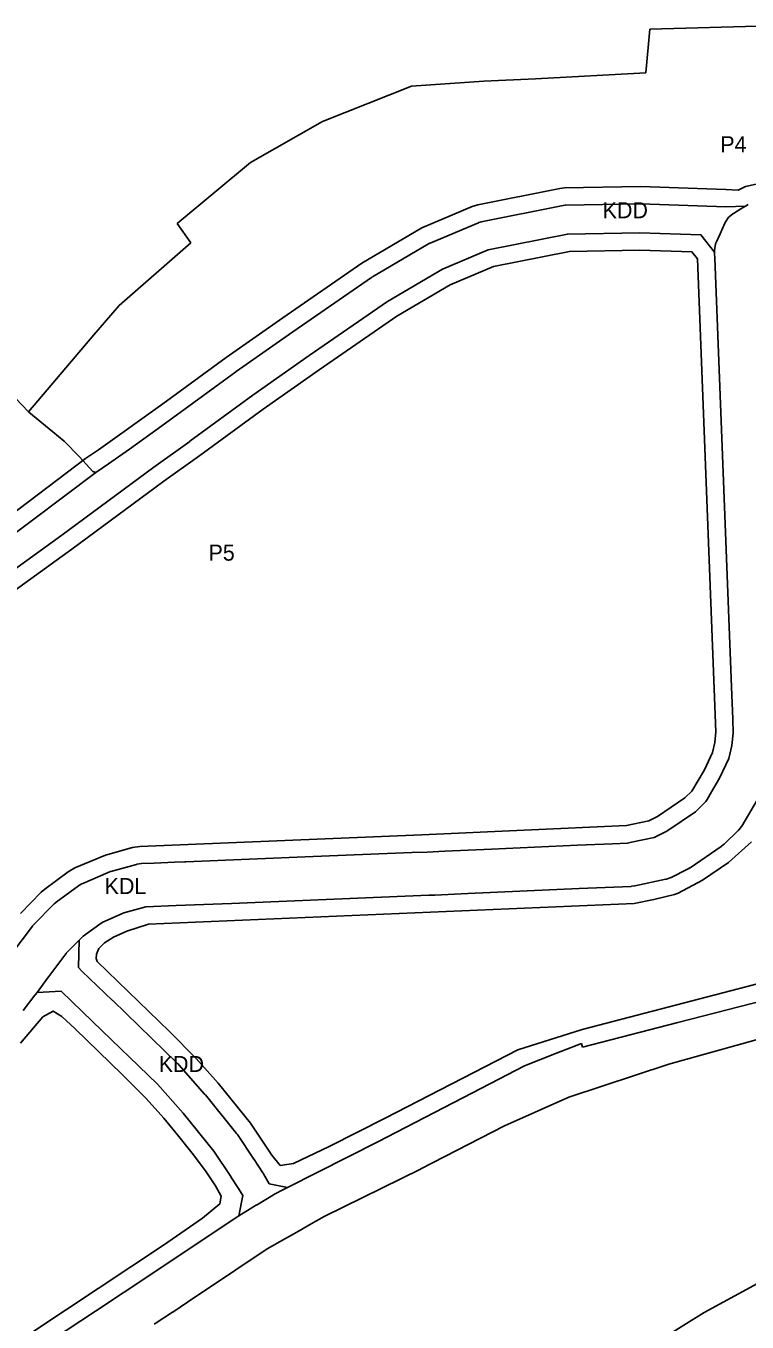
# Model space of a CAD drawing. Extents: x 7428080 to 7432143, y 5545880 to 5549217.
# Drawn here: x 7429660.4 to 7429910.1, y 5546644.6 to 5547093.2 of the extents above; entities that cross this region are included whole.
import ezdxf

# ---------------------------------------------------------------- set-up
doc = ezdxf.new("R2010")
doc.units = 0
for name, color, linetype in [('CZ_L_linie rozgraniczające tereny o różnym przeznaczeniu oraz różnych warunkach ich zabudowy i zagospodarowania', 7, 'Continuous'), ('CZ_L_maksymalne nieprzekraczalne linie zabudowy', 7, 'Continuous'), ('CZ_L_opisy_linie rozgraniczające tereny o różnym przeznaczeniu oraz różnych warunkach ich zabudowy i zagospodarowania', 7, 'Continuous')]:
    doc.layers.add(name, color=color, linetype=linetype)

msp = doc.modelspace()

# ---------------------------------------------------------------- linework, layer by layer
at = {"layer": 'CZ_L_linie rozgraniczające tereny o różnym przeznaczeniu oraz różnych warunkach ich zabudowy i zagospodarowania'}
for p, q in [((7429874.96, 5547076.96), (7429876.37, 5547092.06)), ((7429876.37, 5547092.06), (7429917.87, 5547093.18)), ((7429793.83, 5547072.3), (7429818.9, 5547074.03)), ((7429818.9, 5547074.03), (7429836.84, 5547074.85)), ((7429836.84, 5547074.85), (7429874.96, 5547076.96)), ((7429763.03, 5547060.05), (7429793.83, 5547072.3)), ((7429738.12, 5547045.86), (7429763.03, 5547060.05)), ((7429712.77, 5547024.79), (7429738.12, 5547045.86)), ((7429846.36, 5547031.02), (7429817.99, 5547025.37)), ((7429847.13, 5547031.12), (7429846.36, 5547031.02)), ((7429847.19, 5547031.11), (7429847.13, 5547031.12)), ((7429847.24, 5547031.12), (7429847.19, 5547031.11)), ((7429872.9, 5547031.63), (7429847.24, 5547031.12)), ((7429873.05, 5547031.61), (7429872.9, 5547031.63)), ((7429873.17, 5547031.63), (7429873.05, 5547031.61)), ((7429902.73, 5547030.62), (7429873.17, 5547031.63)), ((7429909.53, 5547030.84), (7429902.73, 5547030.62)), ((7429910.5, 5547031.42), (7429909.53, 5547030.84)), ((7429717.49, 5547018.12), (7429712.77, 5547024.79)), ((7429817.03, 5547025.08), (7429800.36, 5547018.04)), ((7429817.2, 5547025.11), (7429817.03, 5547025.08)), ((7429817.99, 5547025.37), (7429817.2, 5547025.11)), ((7429692.68, 5546996.37), (7429717.49, 5547018.12)), ((7429799.78, 5547017.75), (7429780.38, 5547006.37)), ((7429800.21, 5547017.98), (7429799.78, 5547017.75)), ((7429800.3, 5547018), (7429800.21, 5547017.98)), ((7429800.36, 5547018.04), (7429800.3, 5547018)), ((7429898.8, 5547014.91), (7429898.82, 5547014.42)), ((7429898.82, 5547014.42), (7429898.88, 5547012.83)), ((7429898.88, 5547012.83), (7429904.65, 5546864.42)), ((7429780.07, 5547006.17), (7429752.77, 5546987.33)), ((7429780.29, 5547006.3), (7429780.07, 5547006.17)), ((7429780.38, 5547006.37), (7429780.29, 5547006.3)), ((7429683.9, 5546986.22), (7429692.68, 5546996.37)), ((7429661.31, 5546959.61), (7429683.9, 5546986.22)), ((7429752.73, 5546987.3), (7429733.17, 5546973.53)), ((7429752.75, 5546987.31), (7429752.73, 5546987.3)), ((7429752.77, 5546987.33), (7429752.75, 5546987.31)), ((7429733.09, 5546973.48), (7429711.26, 5546957.51)), ((7429733.13, 5546973.5), (7429733.09, 5546973.48)), ((7429733.17, 5546973.53), (7429733.13, 5546973.5)), ((7429654.57, 5546966.64), (7429661.31, 5546959.61)), ((7429661.43, 5546959.5), (7429661.31, 5546959.61)), ((7429669.66, 5546952.68), (7429661.43, 5546959.5)), ((7429711.26, 5546957.51), (7429705.32, 5546953.27)), ((7429673.58, 5546949.45), (7429669.66, 5546952.68)), ((7429705.32, 5546953.27), (7429696.19, 5546946.75)), ((7429678.95, 5546944.02), (7429673.58, 5546949.45)), ((7429683.5, 5546938.95), (7429678.95, 5546944.02)), ((7429696.19, 5546946.75), (7429688.95, 5546941.57)), ((7429684.54, 5546938.62), (7429651.42, 5546913.65)), ((7429684.54, 5546938.62), (7429683.5, 5546938.95)), ((7429688.95, 5546941.57), (7429684.54, 5546938.62)), ((7429704.61, 5546940.47), (7429704.62, 5546940.48)), ((7429904.65, 5546864.42), (7429904.65, 5546864.42)), ((7429904.65, 5546864.42), (7429904.65, 5546864.41)), ((7429904.65, 5546864.41), (7429905.1, 5546853.23)), ((7429905.1, 5546853.23), (7429905.29, 5546848.45)), ((7429904.83, 5546844.15), (7429903.75, 5546839.6)), ((7429905.29, 5546848.45), (7429904.83, 5546844.15)), ((7429903.75, 5546839.6), (7429900.58, 5546832.8)), ((7429900.58, 5546832.8), (7429897.77, 5546828.05)), ((7429897.77, 5546828.05), (7429896.25, 5546825.48)), ((7429895.83, 5546824.76), (7429892.18, 5546821.22)), ((7429896.25, 5546825.48), (7429895.83, 5546824.76)), ((7429913.68, 5546825.49), (7429908.23, 5546816.26)), ((7429892.18, 5546821.22), (7429882.62, 5546814.75)), ((7429882, 5546814.39), (7429877.89, 5546812.31)), ((7429882.3, 5546814.54), (7429882, 5546814.39)), ((7429882.62, 5546814.75), (7429882.3, 5546814.54)), ((7429906.99, 5546814.7), (7429902.15, 5546810)), ((7429907.01, 5546814.73), (7429906.99, 5546814.7)), ((7429907.05, 5546814.76), (7429907.01, 5546814.73)), ((7429907.13, 5546814.86), (7429907.05, 5546814.76)), ((7429907.28, 5546814.99), (7429907.13, 5546814.86)), ((7429907.38, 5546815.11), (7429907.28, 5546814.99)), ((7429908.14, 5546816.13), (7429907.38, 5546815.11)), ((7429908.17, 5546816.18), (7429908.14, 5546816.13)), ((7429908.23, 5546816.26), (7429908.17, 5546816.18)), ((7429821.53, 5546808.29), (7429805.37, 5546807.55)), ((7429851.32, 5546809.65), (7429821.53, 5546808.29)), ((7429851.34, 5546809.65), (7429851.32, 5546809.65)), ((7429851.32, 5546809.65), (7429851.32, 5546809.65)), ((7429851.32, 5546809.65), (7429851.32, 5546809.65)), ((7429851.35, 5546809.65), (7429851.34, 5546809.65)), ((7429863.48, 5546810.14), (7429851.35, 5546809.65)), ((7429868.7, 5546810.35), (7429863.48, 5546810.14)), ((7429870.11, 5546810.65), (7429868.7, 5546810.35)), ((7429877.89, 5546812.31), (7429870.11, 5546810.65)), ((7429901.13, 5546809.17), (7429890.31, 5546801.84)), ((7429901.21, 5546809.23), (7429901.13, 5546809.17)), ((7429901.27, 5546809.27), (7429901.21, 5546809.23)), ((7429901.8, 5546809.73), (7429901.27, 5546809.27)), ((7429901.96, 5546809.84), (7429901.8, 5546809.73)), ((7429902.1, 5546809.96), (7429901.96, 5546809.84)), ((7429902.15, 5546810), (7429902.1, 5546809.96)), ((7429715.38, 5546803.87), (7429711.79, 5546803.72)), ((7429715.73, 5546803.88), (7429715.38, 5546803.87)), ((7429759.79, 5546805.67), (7429715.73, 5546803.88)), ((7429793.99, 5546807.06), (7429759.79, 5546805.67)), ((7429799.27, 5546807.27), (7429793.99, 5546807.06)), ((7429805.37, 5546807.55), (7429799.27, 5546807.27)), ((7429688.86, 5546800.18), (7429680.02, 5546796.38)), ((7429688.9, 5546800.19), (7429688.86, 5546800.18)), ((7429689.07, 5546800.24), (7429688.9, 5546800.19)), ((7429689.7, 5546800.48), (7429689.07, 5546800.24)), ((7429689.73, 5546800.48), (7429689.7, 5546800.48)), ((7429689.81, 5546800.51), (7429689.73, 5546800.48)), ((7429698.71, 5546802.99), (7429689.81, 5546800.51)), ((7429698.81, 5546803.01), (7429698.71, 5546802.99)), ((7429698.88, 5546803.03), (7429698.81, 5546803.01)), ((7429700.25, 5546803.24), (7429698.88, 5546803.03)), ((7429700.42, 5546803.26), (7429700.25, 5546803.24)), ((7429704.73, 5546803.43), (7429700.42, 5546803.26)), ((7429711.79, 5546803.72), (7429704.73, 5546803.43)), ((7429889.48, 5546801.36), (7429883.78, 5546798.48)), ((7429889.52, 5546801.38), (7429889.48, 5546801.36)), ((7429889.71, 5546801.5), (7429889.52, 5546801.38)), ((7429890.21, 5546801.78), (7429889.71, 5546801.5)), ((7429890.23, 5546801.8), (7429890.21, 5546801.78)), ((7429890.31, 5546801.84), (7429890.23, 5546801.8)), ((7429678.57, 5546795.55), (7429670.85, 5546789.94)), ((7429678.65, 5546795.6), (7429678.57, 5546795.55)), ((7429678.69, 5546795.63), (7429678.65, 5546795.6)), ((7429679.7, 5546796.23), (7429678.69, 5546795.63)), ((7429679.83, 5546796.29), (7429679.7, 5546796.23)), ((7429679.91, 5546796.32), (7429679.83, 5546796.29)), ((7429679.98, 5546796.36), (7429679.91, 5546796.32)), ((7429680, 5546796.37), (7429679.98, 5546796.36)), ((7429680.02, 5546796.38), (7429680, 5546796.37)), ((7429869.94, 5546795.39), (7429851.98, 5546794.66)), ((7429870.07, 5546795.4), (7429869.94, 5546795.39)), ((7429871.07, 5546795.53), (7429870.07, 5546795.4)), ((7429871.1, 5546795.54), (7429871.07, 5546795.53)), ((7429871.2, 5546795.55), (7429871.1, 5546795.54)), ((7429881.96, 5546797.84), (7429871.2, 5546795.55)), ((7429882.05, 5546797.87), (7429881.96, 5546797.84)), ((7429882.12, 5546797.88), (7429882.05, 5546797.87)), ((7429883.39, 5546798.31), (7429882.12, 5546797.88)), ((7429883.55, 5546798.37), (7429883.39, 5546798.31)), ((7429883.65, 5546798.43), (7429883.55, 5546798.37)), ((7429883.73, 5546798.46), (7429883.65, 5546798.43)), ((7429883.75, 5546798.47), (7429883.73, 5546798.46)), ((7429883.78, 5546798.48), (7429883.75, 5546798.47)), ((7429799.9, 5546792.29), (7429731.51, 5546789.51)), ((7429799.91, 5546792.29), (7429799.9, 5546792.29)), ((7429799.93, 5546792.29), (7429799.91, 5546792.29)), ((7429799.94, 5546792.29), (7429799.93, 5546792.29)), ((7429799.93, 5546792.29), (7429799.93, 5546792.29)), ((7429801.91, 5546792.38), (7429799.94, 5546792.29)), ((7429813.43, 5546792.9), (7429801.91, 5546792.38)), ((7429851.98, 5546794.66), (7429813.43, 5546792.9)), ((7429669.9, 5546789.12), (7429663.29, 5546782.37)), ((7429669.93, 5546789.14), (7429669.9, 5546789.12)), ((7429670.11, 5546789.3), (7429669.93, 5546789.14)), ((7429670.15, 5546789.33), (7429670.11, 5546789.3)), ((7429670.73, 5546789.85), (7429670.15, 5546789.33)), ((7429670.78, 5546789.88), (7429670.73, 5546789.85)), ((7429670.85, 5546789.94), (7429670.78, 5546789.88)), ((7429694.32, 5546786.2), (7429686.71, 5546782.93)), ((7429701.9, 5546788.31), (7429694.32, 5546786.2)), ((7429712.4, 5546788.73), (7429701.9, 5546788.31)), ((7429731.51, 5546789.51), (7429712.4, 5546788.73)), ((7429662.65, 5546781.62), (7429651.62, 5546766.91)), ((7429662.69, 5546781.67), (7429662.65, 5546781.62)), ((7429662.7, 5546781.68), (7429662.69, 5546781.67)), ((7429663.09, 5546782.15), (7429662.7, 5546781.68)), ((7429663.11, 5546782.17), (7429663.09, 5546782.15)), ((7429663.14, 5546782.21), (7429663.11, 5546782.17)), ((7429663.21, 5546782.27), (7429663.14, 5546782.21)), ((7429663.26, 5546782.34), (7429663.21, 5546782.27)), ((7429663.28, 5546782.35), (7429663.26, 5546782.34)), ((7429663.29, 5546782.37), (7429663.28, 5546782.35)), ((7429686.71, 5546782.93), (7429680.18, 5546778.18)), ((7429679.93, 5546777.93), (7429678.82, 5546776.79)), ((7429680.18, 5546778.18), (7429679.93, 5546777.93)), ((7429674.35, 5546772.23), (7429678.82, 5546776.79)), ((7429678.82, 5546776.79), (7429678.62, 5546767.27)), ((7429668.32, 5546764.19), (7429673.86, 5546771.57)), ((7429673.86, 5546771.57), (7429674.28, 5546772.14)), ((7429674.28, 5546772.14), (7429674.3, 5546772.16)), ((7429674.3, 5546772.16), (7429674.35, 5546772.23)), ((7429664.21, 5546758.69), (7429667.86, 5546763.57)), ((7429667.86, 5546763.57), (7429668.3, 5546764.15)), ((7429668.3, 5546764.15), (7429668.32, 5546764.19)), ((7429678.62, 5546767.27), (7429679.73, 5546766.06)), ((7429679.73, 5546766.06), (7429690.38, 5546755.88)), ((7429664.21, 5546758.69), (7429672.53, 5546759.11)), ((7429672.53, 5546759.11), (7429672.58, 5546759.06)), ((7429672.58, 5546759.06), (7429683.46, 5546748.67)), ((7429659.42, 5546752.44), (7429663.45, 5546757.68)), ((7429663.45, 5546757.68), (7429663.54, 5546757.81)), ((7429663.54, 5546757.81), (7429663.55, 5546757.82)), ((7429663.55, 5546757.82), (7429663.56, 5546757.83)), ((7429663.56, 5546757.83), (7429663.6, 5546757.88)), ((7429663.6, 5546757.88), (7429664.21, 5546758.69)), ((7429690.38, 5546755.88), (7429690.41, 5546755.86)), ((7429690.41, 5546755.86), (7429713.02, 5546733.95)), ((7429886.04, 5546748.22), (7429924.76, 5546758.19)), ((7429683.46, 5546748.67), (7429705.91, 5546726.91)), ((7429853.09, 5546739.73), (7429886.04, 5546748.22)), ((7429934.88, 5546748.35), (7429882.96, 5546733.84)), ((7429844.07, 5546737.68), (7429852.75, 5546741.04)), ((7429852.75, 5546741.04), (7429853.09, 5546739.73)), ((7429832.96, 5546733.29), (7429844.07, 5546737.68)), ((7429713.02, 5546733.95), (7429713.16, 5546733.81)), ((7429713.16, 5546733.81), (7429713.29, 5546733.66)), ((7429713.29, 5546733.66), (7429722.36, 5546723.36)), ((7429818.1, 5546725.51), (7429832.96, 5546733.29)), ((7429882.96, 5546733.84), (7429848.3, 5546722.48)), ((7429705.91, 5546726.91), (7429714.78, 5546716.83)), ((7429722.36, 5546723.36), (7429722.44, 5546723.26)), ((7429722.44, 5546723.26), (7429722.49, 5546723.21)), ((7429722.49, 5546723.21), (7429733.33, 5546709.84)), ((7429782.17, 5546707.01), (7429818.1, 5546725.51)), ((7429848.3, 5546722.48), (7429826.04, 5546712.45)), ((7429714.78, 5546716.83), (7429725.42, 5546703.73)), ((7429733.33, 5546709.84), (7429733.49, 5546709.64)), ((7429733.49, 5546709.64), (7429733.62, 5546709.46)), ((7429826.04, 5546712.45), (7429797.11, 5546697.57)), ((7429733.62, 5546709.46), (7429739.24, 5546701)), ((7429750.95, 5546691.21), (7429782.17, 5546707.01)), ((7429725.42, 5546703.73), (7429731.27, 5546694.94)), ((7429739.24, 5546701), (7429739.38, 5546700.8)), ((7429739.38, 5546700.8), (7429742.44, 5546696.2)), ((7429742.44, 5546696.2), (7429742.5, 5546696.11)), ((7429797.03, 5546697.52), (7429763.67, 5546681.14)), ((7429797.07, 5546697.56), (7429797.03, 5546697.52)), ((7429797.11, 5546697.57), (7429797.07, 5546697.56)), ((7429731.27, 5546694.94), (7429731.34, 5546694.82)), ((7429731.34, 5546694.82), (7429734.02, 5546690.8)), ((7429742.5, 5546696.11), (7429742.6, 5546695.93)), ((7429742.6, 5546695.93), (7429744.59, 5546692.47)), ((7429744.59, 5546692.47), (7429750.95, 5546691.21)), ((7429734.02, 5546690.8), (7429735.44, 5546688.34)), ((7429735.44, 5546688.34), (7429734.05, 5546681.31)), ((7429746.62, 5546688.95), (7429740.23, 5546685.1)), ((7429746.63, 5546688.93), (7429746.62, 5546688.95)), ((7429749.12, 5546690.27), (7429746.63, 5546688.93)), ((7429750.95, 5546691.21), (7429749.12, 5546690.28)), ((7429749.12, 5546690.28), (7429749.12, 5546690.27)), ((7429738.06, 5546683.78), (7429734.05, 5546681.31)), ((7429740.19, 5546685.15), (7429738.05, 5546683.8)), ((7429738.05, 5546683.8), (7429738.06, 5546683.78)), ((7429740.23, 5546685.1), (7429740.19, 5546685.15)), ((7429733.43, 5546680.94), (7429714.83, 5546668.51)), ((7429734.05, 5546681.31), (7429733.43, 5546680.94)), ((7429760, 5546679.05), (7429754.16, 5546675.73)), ((7429763.67, 5546681.14), (7429760, 5546679.05)), ((7429754.16, 5546675.73), (7429750.2, 5546673.48)), ((7429743.94, 5546669.92), (7429733.09, 5546662.72)), ((7429750.2, 5546673.48), (7429743.94, 5546669.92)), ((7429714.83, 5546668.51), (7429703.96, 5546661.25)), ((7429703.96, 5546661.25), (7429684.51, 5546648.33)), ((7429733.09, 5546662.72), (7429721.8, 5546655.21)), ((7429895.22, 5546647.94), (7429920.47, 5546661.62)), ((7429718.88, 5546653.25), (7429711.22, 5546648.04)), ((7429721.8, 5546655.21), (7429718.88, 5546653.25)), ((7429684.51, 5546648.33), (7429664.19, 5546634.98)), ((7429711.15, 5546647.99), (7429704.83, 5546643.84)), ((7429711.17, 5546648.01), (7429711.15, 5546647.99)), ((7429711.22, 5546648.04), (7429711.17, 5546648.01)), ((7429881.09, 5546639.13), (7429895.22, 5546647.94))]:
    msp.add_line(p, q, dxfattribs=at)
for points in [[(7429909.53, 5547030.84), (7429907.9, 5547029.86), (7429905.33, 5547028.3), (7429905.25, 5547028.24), (7429905.15, 5547028.18), (7429903.84, 5547027.11), (7429903.69, 5547026.96), (7429903.54, 5547026.77), (7429902.48, 5547025.17), (7429902.41, 5547025.02), (7429902.37, 5547024.96), (7429900.7, 5547021.25), (7429899.45, 5547018.49), (7429899.44, 5547018.44), (7429899.44, 5547018.44), (7429899.41, 5547018.39), (7429899.37, 5547018.24), (7429899.31, 5547018.12), (7429899.25, 5547017.99), (7429899.24, 5547017.96), (7429899.18, 5547017.71), (7429898.81, 5547015.41), (7429898.8, 5547015.12), (7429898.8, 5547014.94), (7429898.8, 5547014.92), (7429898.8, 5547014.91)], [(7429575.21, 5546869.82), (7429606.33, 5546874.9), (7429626.24, 5546883.33), (7429672.75, 5546916.96), (7429704.62, 5546940.48), (7429717.09, 5546949.4), (7429717.11, 5546949.41), (7429717.14, 5546949.43), (7429738.96, 5546965.38), (7429758.47, 5546979.11), (7429785.6, 5546997.84), (7429804.56, 5547008.96), (7429820.45, 5547015.66), (7429847.88, 5547021.13), (7429872.96, 5547021.63), (7429894.1, 5547020.91), (7429898.8, 5547014.91)]]:
    msp.add_lwpolyline(points, dxfattribs=at)
at = {"layer": 'CZ_L_maksymalne nieprzekraczalne linie zabudowy'}
for points in [[(7429647.87, 5546918.48), (7429681.01, 5546943.47), (7429685.54, 5546946.51), (7429707.74, 5546962.38), (7429729.71, 5546978.44), (7429749.28, 5546992.21), (7429776.66, 5547011.11), (7429797.43, 5547023.29), (7429814.87, 5547030.67), (7429816.82, 5547031.26), (7429845.19, 5547036.91), (7429846.89, 5547037.11), (7429873.32, 5547037.63), (7429902.74, 5547036.62), (7429907.03, 5547036.34), (7429909.53, 5547037.57), (7429913.23, 5547038.44)], [(7429658.48, 5546785.99), (7429665.62, 5546793.33), (7429666.89, 5546794.45), (7429675.05, 5546800.41), (7429677.31, 5546801.74), (7429687.91, 5546806.2), (7429697.29, 5546808.82), (7429699.84, 5546809.23), (7429797.42, 5546813.2), (7429868.35, 5546816.41), (7429876.04, 5546818.09), (7429879.06, 5546819.62), (7429888.48, 5546825.99), (7429890.89, 5546828.33), (7429895.34, 5546835.77), (7429898.08, 5546841.66), (7429898.91, 5546845.23), (7429899.27, 5546848.87), (7429892.89, 5547012.53), (7429890.95, 5547015.01), (7429872.92, 5547015.63), (7429848.53, 5547015.14), (7429822.22, 5547009.9), (7429807.25, 5547003.58), (7429788.83, 5546992.78), (7429761.89, 5546974.18), (7429742.46, 5546960.51), (7429720.63, 5546944.55), (7429708.13, 5546935.62), (7429676.28, 5546912.11), (7429629.45, 5546878.26)], [(7429911.59, 5546810.84), (7429903.68, 5546803.65), (7429894.67, 5546797.56), (7429886.23, 5546793.01), (7429884.99, 5546792.55), (7429877.84, 5546790.86), (7429871.03, 5546789.48), (7429702.84, 5546782.34), (7429695.27, 5546779.91), (7429690.68, 5546777.82), (7429687.58, 5546775.85), (7429685.65, 5546773.88), (7429684.84, 5546771.93), (7429684.69, 5546770.42), (7429685.08, 5546769.36), (7429710.07, 5546745.15), (7429719.35, 5546735.86), (7429726.94, 5546727.23), (7429738.13, 5546713.44), (7429745.47, 5546702.35), (7429748.4, 5546698.79)], [(7429748.4, 5546698.79), (7429753.07, 5546699.46), (7429765.42, 5546705.4), (7429784.79, 5546715.2), (7429830.7, 5546738.85), (7429852.92, 5546745.87), (7429923.38, 5546764.18)], [(7429662.79, 5546641.23), (7429707.96, 5546671.22), (7429721.5, 5546680.55), (7429727.5, 5546685.48), (7429727.93, 5546688.19), (7429726.02, 5546691.7), (7429722.74, 5546696.56), (7429718.35, 5546702.48), (7429713.32, 5546708.86), (7429708.11, 5546715.12), (7429701.95, 5546721.91), (7429693.71, 5546730.28), (7429677.46, 5546746.07), (7429672.81, 5546750.31), (7429669.85, 5546752.21), (7429666.25, 5546750.2), (7429658.48, 5546741.07)]]:
    msp.add_lwpolyline(points, dxfattribs=at)

# ---------------------------------------------------------------- texts
at = {"layer": 'CZ_L_opisy_linie rozgraniczające tereny o różnym przeznaczeniu oraz różnych warunkach ich zabudowy i zagospodarowania'}
for s, p in [('P4', (7429900.8, 5547049.47)), ('KDD', (7429860.07, 5547026.61)), ('P5', (7429723.6, 5546908.11)), ('KDL', (7429687.62, 5546792.73)), ('KDD', (7429706.36, 5546731.14))]:
    msp.add_text(s, height=5.549, dxfattribs=at).set_placement(p)

doc.saveas('drawing.dxf')
